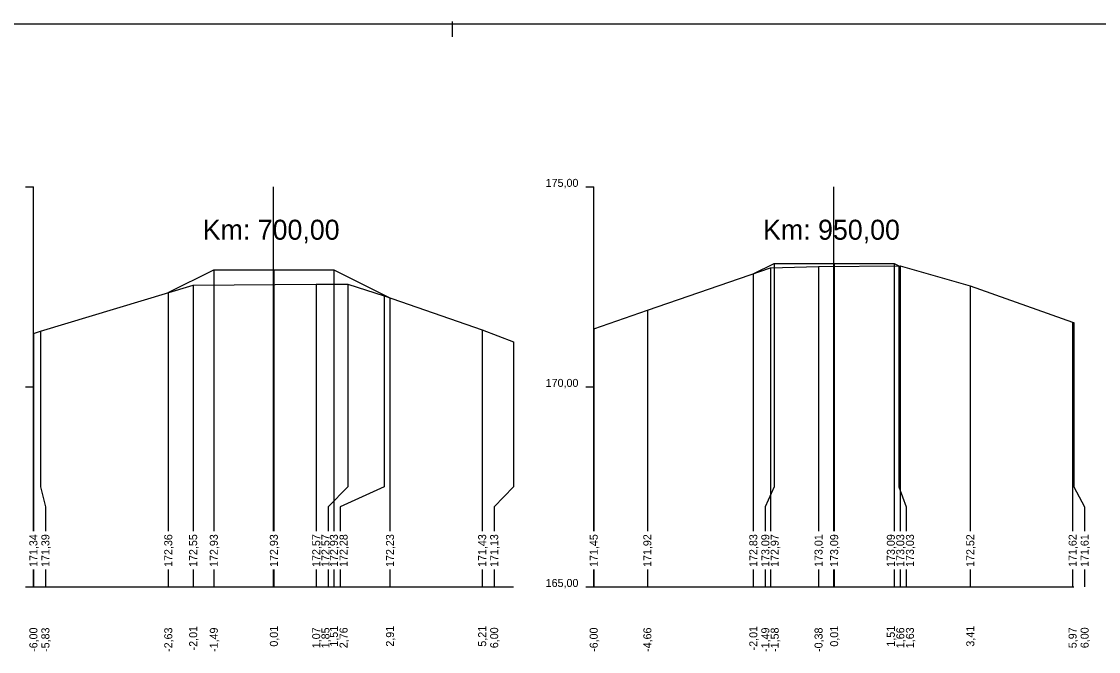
# Model space of a CAD drawing. Extents: x -614174 to -599765, y -1185887 to -1181080.
# Drawn here: x -601053.72 to -601026.82, y -1184398.95 to -1184383.21 of the extents above; entities that cross this region are included whole.
import ezdxf

# ---------------------------------------------------------------- set-up
doc = ezdxf.new("R2010")
doc.units = 0
for name, color, linetype in [('11', 7, 'Continuous'), ('16', 7, 'Continuous'), ('21', 7, 'Continuous'), ('28', 7, 'Continuous'), ('59', 7, 'Continuous'), ('8', 7, 'Continuous'), ('návrh', 7, 'Continuous')]:
    doc.layers.add(name, color=color, linetype=linetype)

msp = doc.modelspace()

# ---------------------------------------------------------------- linework, layer by layer
for points in [[(-601039.427, -1184390.89), (-601038.087, -1184390.426), (-601035.009, -1184389.367), (-601033.809, -1184389.332), (-601031.767, -1184389.314), (-601030.018, -1184389.817), (-601027.461, -1184390.724), (-601027.427, -1184390.733)], [(-601035.439, -1184389.515), (-601034.919, -1184389.255), (-601033.419, -1184389.255), (-601031.919, -1184389.255), (-601031.8, -1184389.315)], [(-601034.919, -1184389.255), (-601034.919, -1184389.255), (-601034.919, -1184389.255)], [(-601033.419, -1184389.255), (-601033.419, -1184389.255), (-601033.419, -1184389.255)], [(-601031.919, -1184389.255), (-601031.919, -1184389.255), (-601031.919, -1184389.255)], [(-601050.057, -1184389.985), (-601048.919, -1184389.416), (-601047.419, -1184389.416), (-601045.919, -1184389.416), (-601044.517, -1184390.117)], [(-601048.919, -1184389.416), (-601048.919, -1184389.416), (-601048.919, -1184389.416)], [(-601047.419, -1184389.416), (-601047.419, -1184389.416), (-601047.419, -1184389.416)], [(-601045.919, -1184389.416), (-601045.919, -1184389.416), (-601045.919, -1184389.416)], [(-601035.44, -1184389.515), (-601035.439, -1184389.515), (-601035.439, -1184389.515)], [(-601053.427, -1184391.004), (-601053.253, -1184390.952), (-601049.435, -1184389.797), (-601046.36, -1184389.774), (-601045.574, -1184389.772), (-601044.666, -1184390.066), (-601042.214, -1184390.915), (-601041.427, -1184391.214)], [(-601050.057, -1184389.985), (-601050.057, -1184389.985), (-601050.057, -1184389.985)]]:
    msp.add_lwpolyline(points)
at = {"layer": '11'}
for points in [[(-601034.919, -1184389.255), (-601034.919, -1184394.842), (-601035.139, -1184395.342), (-601035.139, -1184395.944)], [(-601033.809, -1184389.332), (-601033.809, -1184394.842), (-601033.809, -1184395.342), (-601033.809, -1184395.944)], [(-601033.419, -1184389.255), (-601033.419, -1184394.842), (-601033.419, -1184395.342), (-601033.419, -1184395.944)], [(-601031.919, -1184389.255), (-601031.919, -1184394.842), (-601031.919, -1184395.342), (-601031.919, -1184395.944)], [(-601031.8, -1184389.315), (-601031.8, -1184394.842), (-601031.619, -1184395.342), (-601031.619, -1184395.944)], [(-601031.767, -1184389.314), (-601031.767, -1184394.842), (-601031.767, -1184395.342), (-601031.767, -1184395.944)], [(-601048.919, -1184389.416), (-601048.919, -1184394.842), (-601048.919, -1184395.342), (-601048.919, -1184395.944)], [(-601047.419, -1184389.416), (-601047.419, -1184394.842), (-601047.419, -1184395.342), (-601047.419, -1184395.944)], [(-601045.919, -1184389.416), (-601045.919, -1184394.842), (-601045.919, -1184395.342), (-601045.919, -1184395.944)], [(-601035.439, -1184389.515), (-601035.439, -1184394.842), (-601035.439, -1184395.342), (-601035.439, -1184395.944)], [(-601035.009, -1184389.367), (-601035.009, -1184394.842), (-601035.009, -1184395.342), (-601035.009, -1184395.944)], [(-601049.435, -1184389.797), (-601049.435, -1184394.842), (-601049.435, -1184395.342), (-601049.435, -1184395.944)], [(-601046.36, -1184389.774), (-601046.36, -1184394.842), (-601046.36, -1184395.342), (-601046.36, -1184395.944)], [(-601045.574, -1184389.772), (-601045.574, -1184394.842), (-601046.06, -1184395.342), (-601046.06, -1184395.944)], [(-601030.018, -1184389.817), (-601030.018, -1184394.842), (-601030.018, -1184395.342), (-601030.018, -1184395.944)], [(-601050.057, -1184389.985), (-601050.057, -1184394.842), (-601050.057, -1184395.342), (-601050.057, -1184395.944)], [(-601044.666, -1184390.066), (-601044.666, -1184394.842), (-601045.76, -1184395.342), (-601045.76, -1184395.944)], [(-601044.517, -1184390.117), (-601044.517, -1184394.842), (-601044.517, -1184395.342), (-601044.517, -1184395.944)], [(-601038.087, -1184390.426), (-601038.087, -1184394.842), (-601038.087, -1184395.342), (-601038.087, -1184395.944)], [(-601053.253, -1184390.952), (-601053.253, -1184394.842), (-601053.127, -1184395.342), (-601053.127, -1184395.944)], [(-601042.214, -1184390.915), (-601042.214, -1184394.842), (-601042.214, -1184395.342), (-601042.214, -1184395.944)], [(-601039.427, -1184390.89), (-601039.427, -1184394.842), (-601039.427, -1184395.342), (-601039.427, -1184395.944)], [(-601027.461, -1184390.724), (-601027.461, -1184394.842), (-601027.461, -1184395.342), (-601027.461, -1184395.944)], [(-601027.427, -1184390.733), (-601027.427, -1184394.842), (-601027.161, -1184395.342), (-601027.161, -1184395.944)], [(-601053.427, -1184391.004), (-601053.427, -1184394.842), (-601053.427, -1184395.342), (-601053.427, -1184395.944)], [(-601041.427, -1184391.214), (-601041.427, -1184394.842), (-601041.914, -1184395.342), (-601041.914, -1184395.944)], [(-601053.427, -1184396.902), (-601053.427, -1184397.342)], [(-601053.127, -1184396.902), (-601053.127, -1184397.342)], [(-601050.057, -1184396.902), (-601050.057, -1184397.342)], [(-601049.435, -1184396.902), (-601049.435, -1184397.342)], [(-601048.919, -1184396.902), (-601048.919, -1184397.342)], [(-601047.419, -1184396.902), (-601047.419, -1184397.342)], [(-601046.36, -1184396.902), (-601046.36, -1184397.342)], [(-601046.06, -1184396.902), (-601046.06, -1184397.342)], [(-601045.919, -1184396.902), (-601045.919, -1184397.342)], [(-601045.76, -1184396.902), (-601045.76, -1184397.342)], [(-601044.517, -1184396.902), (-601044.517, -1184397.342)], [(-601042.214, -1184396.902), (-601042.214, -1184397.342)], [(-601041.914, -1184396.902), (-601041.914, -1184397.342)], [(-601039.427, -1184396.902), (-601039.427, -1184397.342)], [(-601038.087, -1184396.902), (-601038.087, -1184397.342)], [(-601035.439, -1184396.902), (-601035.439, -1184397.342)], [(-601035.139, -1184396.902), (-601035.139, -1184397.342)], [(-601035.009, -1184396.902), (-601035.009, -1184397.342)], [(-601033.809, -1184396.902), (-601033.809, -1184397.342)], [(-601033.419, -1184396.902), (-601033.419, -1184397.342)], [(-601031.919, -1184396.902), (-601031.919, -1184397.342)], [(-601031.767, -1184396.902), (-601031.767, -1184397.342)], [(-601031.619, -1184396.902), (-601031.619, -1184397.342)], [(-601030.018, -1184396.902), (-601030.018, -1184397.342)], [(-601027.461, -1184396.902), (-601027.461, -1184397.342)], [(-601027.161, -1184396.902), (-601027.161, -1184397.342)]]:
    msp.add_lwpolyline(points, dxfattribs=at)
at = {"layer": '16'}
for p, q in [((-601053.427, -1184397.342), (-601041.427, -1184397.342)), ((-601039.427, -1184397.342), (-601027.427, -1184397.342))]:
    msp.add_line(p, q, dxfattribs=at)
for points in [[(-601031.8, -1184389.315), (-601031.8, -1184389.315), (-601031.8, -1184389.315)], [(-601044.517, -1184390.117), (-601044.517, -1184390.117), (-601044.518, -1184390.117)]]:
    msp.add_lwpolyline(points, dxfattribs=at)
at = {"layer": '21'}
for p, q in [((-601053.627, -1184387.342), (-601053.427, -1184387.342)), ((-601039.627, -1184387.342), (-601039.427, -1184387.342)), ((-601053.627, -1184392.342), (-601053.427, -1184392.342)), ((-601039.627, -1184392.342), (-601039.427, -1184392.342)), ((-601053.627, -1184397.342), (-601053.427, -1184397.342)), ((-601039.627, -1184397.342), (-601039.427, -1184397.342))]:
    msp.add_line(p, q, dxfattribs=at)
at = {"layer": '28'}
for p, q in [((-601047.427, -1184395.944), (-601047.427, -1184387.342)), ((-601033.427, -1184395.944), (-601033.427, -1184387.342)), ((-601047.427, -1184397.342), (-601047.427, -1184396.902)), ((-601033.427, -1184397.342), (-601033.427, -1184396.902))]:
    msp.add_line(p, q, dxfattribs=at)
at = {"layer": '8'}
for p, q in [((-601053.427, -1184395.944), (-601053.427, -1184387.342)), ((-601039.427, -1184395.944), (-601039.427, -1184387.342)), ((-601053.427, -1184397.342), (-601053.427, -1184396.902)), ((-601039.427, -1184397.342), (-601039.427, -1184396.902))]:
    msp.add_line(p, q, dxfattribs=at)
at = {"layer": 'návrh'}
for p, q in [((-601084.957, -1184383.271), (-600937.957, -1184383.271)), ((-601042.957, -1184383.59), (-601042.957, -1184383.209))]:
    msp.add_line(p, q, dxfattribs=at)

# ---------------------------------------------------------------- texts
at = {"layer": '16'}
for s, p in [('171,34', (-601053.327, -1184396.842)), ('171,39', (-601053.027, -1184396.842)), ('172,36', (-601049.957, -1184396.842)), ('172,55', (-601049.335, -1184396.842)), ('172,93', (-601048.819, -1184396.842)), ('172,93', (-601047.319, -1184396.842)), ('172,57', (-601046.26, -1184396.842)), ('172,57', (-601046.03, -1184396.842)), ('172,93', (-601045.819, -1184396.842)), ('172,28', (-601045.577, -1184396.842)), ('172,23', (-601044.417, -1184396.842)), ('171,43', (-601042.114, -1184396.842)), ('171,13', (-601041.814, -1184396.842)), ('171,45', (-601039.327, -1184396.842)), ('171,92', (-601037.987, -1184396.842)), ('172,83', (-601035.339, -1184396.842)), ('173,09', (-601035.039, -1184396.842)), ('172,97', (-601034.805, -1184396.842)), ('173,01', (-601033.709, -1184396.842)), ('173,09', (-601033.319, -1184396.842)), ('173,09', (-601031.903, -1184396.842)), ('173,03', (-601031.667, -1184396.842)), ('173,03', (-601031.426, -1184396.842)), ('172,52', (-601029.918, -1184396.842)), ('171,62', (-601027.361, -1184396.842)), ('171,61', (-601027.061, -1184396.842))]:
    msp.add_text(s, height=0.2, rotation=90, dxfattribs=at).set_placement(p)
at = {"layer": '21'}
for s, p in [('175,00', (-601040.627, -1184387.342)), ('170,00', (-601040.627, -1184392.342)), ('165,00', (-601040.627, -1184397.342))]:
    msp.add_text(s, height=0.2, dxfattribs=at).set_placement(p)
at = {"layer": '28'}
for s, p in [('Km: 700,00', (-601049.196, -1184388.663)), ('Km: 950,00', (-601035.196, -1184388.663))]:
    msp.add_text(s, height=0.5, dxfattribs=at).set_placement(p)
at = {"layer": '59'}
for s, p in [('-6,00', (-601053.327, -1184398.965)), ('-5,83', (-601053.027, -1184398.966)), ('-2,63', (-601049.957, -1184398.966)), ('-2,01', (-601049.335, -1184398.927)), ('-1,49', (-601048.819, -1184398.966)), ('0,01', (-601047.319, -1184398.834)), ('1,07', (-601046.26, -1184398.873)), ('1,85', (-601046.03, -1184398.875)), ('1,51', (-601045.819, -1184398.834)), ('2,76', (-601045.577, -1184398.873)), ('2,91', (-601044.417, -1184398.834)), ('5,21', (-601042.114, -1184398.834)), ('6,00', (-601041.814, -1184398.872)), ('-6,00', (-601039.327, -1184398.965)), ('-4,66', (-601037.987, -1184398.966)), ('-2,01', (-601035.339, -1184398.927)), ('-1,49', (-601035.039, -1184398.966)), ('-1,58', (-601034.805, -1184398.966)), ('-0,38', (-601033.709, -1184398.966)), ('0,01', (-601033.319, -1184398.834)), ('1,51', (-601031.903, -1184398.834)), ('1,66', (-601031.667, -1184398.873)), ('1,63', (-601031.426, -1184398.873)), ('3,41', (-601029.918, -1184398.834)), ('5,97', (-601027.361, -1184398.873)), ('6,00', (-601027.061, -1184398.872))]:
    msp.add_text(s, height=0.2, rotation=90, dxfattribs=at).set_placement(p)

doc.saveas('drawing.dxf')
